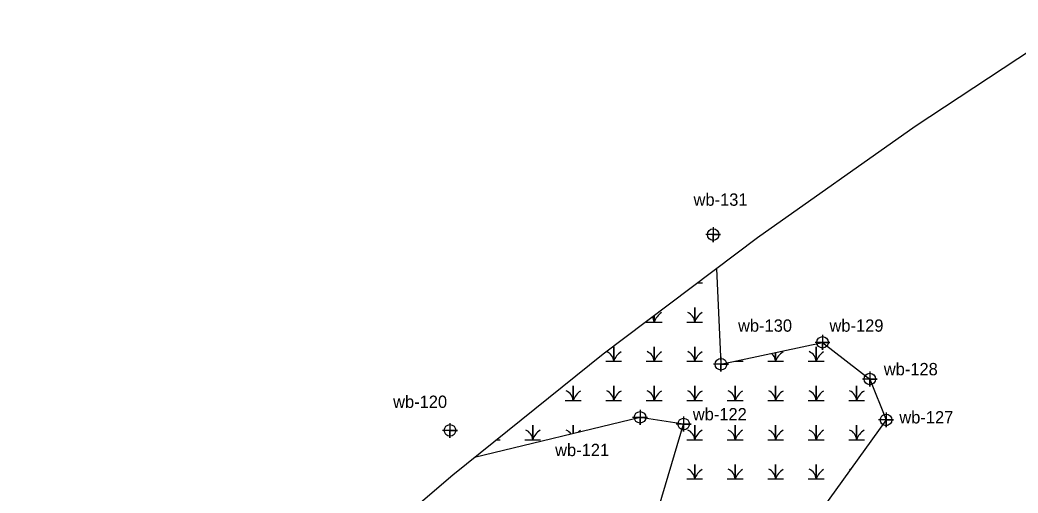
# Model space of a CAD drawing. Extents: x 2379288 to 2381905, y 330670 to 333511.
# Drawn here: x 2380487.2 to 2380892.7, y 332911.6 to 333103.7 of the extents above; entities that cross this region are included whole.
import ezdxf

# ---------------------------------------------------------------- set-up
doc = ezdxf.new("R2010")
doc.units = 0
for name, color, linetype in [('Default', 7, 'Continuous'), ('Exist Environmental Wetland Boundary', 7, 'Continuous'), ('Exist Environmental Wetland Boundary Cogo Number', 7, 'Continuous'), ('Exist Environmental Wetland Boundary Cogo Point CELL', 7, 'Continuous'), ('Exist Hydro Swamp or Marsh', 7, 'Continuous')]:
    doc.layers.add(name, color=color, linetype=linetype)

msp = doc.modelspace()

# ---------------------------------------------------------------- linework, layer by layer
at = {"layer": 'Default'}
msp.add_lwpolyline([(2379288.07, 330873.37), (2380109.3, 332268.58), (2380147.86, 332331.82), (2380190.73, 332397.51), (2380235.65, 332461.81), (2380282.57, 332524.66), (2380331.46, 332586), (2380382.25, 332645.77), (2380434.91, 332703.9), (2380489.37, 332760.35), (2380545.59, 332815.05), (2380603.5, 332867.95), (2380663.06, 332918.99), (2380724.19, 332968.13), (2380786.85, 333015.32), (2380850.96, 333060.51), (2380916.47, 333103.65)], dxfattribs=at)
at = {"layer": 'Exist Environmental Wetland Boundary'}
msp.add_lwpolyline([(2380770.18, 333002.77), (2380771.99, 332963.9), (2380813.28, 332972.8), (2380832.48, 332957.91), (2380839.06, 332941.31), (2380810.01, 332900.93), (2380770.09, 332869.86), (2380731.49, 332867.02), (2380743.29, 332893.96), (2380756.83, 332939.63), (2380739.11, 332942.35), (2380671.81, 332926.03)], dxfattribs=at)
at = {"layer": 'Exist Environmental Wetland Boundary Cogo Point CELL'}
for points in [[(2380768.82, 333019.52), (2380768.82, 333013.52), (2380768.82, 333016.52), (2380771.82, 333016.52), (2380765.82, 333016.52)], [(2380813.28, 332975.8), (2380813.28, 332969.8), (2380813.28, 332972.8), (2380816.28, 332972.8), (2380810.28, 332972.8)], [(2380771.99, 332966.9), (2380771.99, 332960.9), (2380771.99, 332963.9), (2380774.99, 332963.9), (2380768.99, 332963.9)], [(2380832.48, 332960.91), (2380832.48, 332954.91), (2380832.48, 332957.91), (2380835.48, 332957.91), (2380829.48, 332957.91)], [(2380739.11, 332945.35), (2380739.11, 332939.35), (2380739.11, 332942.35), (2380742.11, 332942.35), (2380736.11, 332942.35)], [(2380756.83, 332942.63), (2380756.83, 332936.63), (2380756.83, 332939.63), (2380759.83, 332939.63), (2380753.83, 332939.63)], [(2380839.06, 332944.31), (2380839.06, 332938.31), (2380839.06, 332941.31), (2380842.06, 332941.31), (2380836.06, 332941.31)], [(2380661.89, 332940.05), (2380661.89, 332934.05), (2380661.89, 332937.05), (2380664.89, 332937.05), (2380658.89, 332937.05)]]:
    msp.add_lwpolyline(points, dxfattribs=at)
for centre in [(2380768.82, 333016.52), (2380813.28, 332972.8), (2380771.99, 332963.9), (2380832.48, 332957.91), (2380739.11, 332942.35), (2380756.83, 332939.63), (2380839.06, 332941.31), (2380661.89, 332937.05)]:
    msp.add_circle(centre, 2.34, dxfattribs=at)
at = {"layer": 'Exist Hydro Swamp or Marsh'}
for p, q in [((2380762.44, 332996.94), (2380764.53, 332996.94)), ((2380680.82, 332933.27), (2380682.27, 332933.27))]:
    msp.add_line(p, q, dxfattribs=at)
for points in [[(2380758.08, 332981.02), (2380761.31, 332981.02), (2380761.31, 332986.94), (2380761.31, 332981.02), (2380764.53, 332981.02)], [(2380741.63, 332981.02), (2380744.85, 332981.02), (2380744.85, 332983.69)], [(2380744.85, 332983.69), (2380744.85, 332981.02), (2380748.08, 332981.02)], [(2380725.18, 332965.1), (2380728.4, 332965.1), (2380728.4, 332971.02), (2380728.4, 332965.1), (2380731.63, 332965.1)], [(2380741.63, 332965.1), (2380744.85, 332965.1), (2380744.85, 332971.02), (2380744.85, 332965.1), (2380748.08, 332965.1)], [(2380758.08, 332965.1), (2380761.31, 332965.1), (2380761.31, 332971.02), (2380761.31, 332965.1), (2380764.53, 332965.1)], [(2380807.43, 332965.1), (2380810.66, 332965.1), (2380810.66, 332971.02), (2380810.66, 332965.1), (2380813.88, 332965.1)], [(2380790.98, 332965.1), (2380794.21, 332965.1), (2380794.21, 332968.68)], [(2380794.21, 332968.68), (2380794.21, 332965.1), (2380797.43, 332965.1)], [(2380777.61, 332965.1), (2380777.76, 332965.1), (2380777.76, 332965.14)], [(2380777.76, 332965.14), (2380777.76, 332965.1), (2380780.98, 332965.1)], [(2380708.73, 332949.19), (2380711.95, 332949.19), (2380711.95, 332955.1), (2380711.95, 332949.19), (2380715.18, 332949.19)], [(2380725.18, 332949.19), (2380728.4, 332949.19), (2380728.4, 332955.1), (2380728.4, 332949.19), (2380731.63, 332949.19)], [(2380741.63, 332949.19), (2380744.85, 332949.19), (2380744.85, 332955.1), (2380744.85, 332949.19), (2380748.08, 332949.19)], [(2380758.08, 332949.19), (2380761.31, 332949.19), (2380761.31, 332955.1), (2380761.31, 332949.19), (2380764.53, 332949.19)], [(2380774.53, 332949.19), (2380777.76, 332949.19), (2380777.76, 332955.1), (2380777.76, 332949.19), (2380780.98, 332949.19)], [(2380790.98, 332949.19), (2380794.21, 332949.19), (2380794.21, 332955.1), (2380794.21, 332949.19), (2380797.43, 332949.19)], [(2380807.43, 332949.19), (2380810.66, 332949.19), (2380810.66, 332955.1), (2380810.66, 332949.19), (2380813.88, 332949.19)], [(2380823.88, 332949.19), (2380827.11, 332949.19), (2380827.11, 332955.1), (2380827.11, 332949.19), (2380830.34, 332949.19)], [(2380692.27, 332933.27), (2380695.5, 332933.27), (2380695.5, 332939.19), (2380695.5, 332933.27), (2380698.73, 332933.27)], [(2380711.95, 332935.76), (2380711.95, 332939.19), (2380711.95, 332935.76)], [(2380758.08, 332933.27), (2380761.31, 332933.27), (2380761.31, 332939.19), (2380761.31, 332933.27), (2380764.53, 332933.27)], [(2380774.53, 332933.27), (2380777.76, 332933.27), (2380777.76, 332939.19), (2380777.76, 332933.27), (2380780.98, 332933.27)], [(2380790.98, 332933.27), (2380794.21, 332933.27), (2380794.21, 332939.19), (2380794.21, 332933.27), (2380797.43, 332933.27)], [(2380807.43, 332933.27), (2380810.66, 332933.27), (2380810.66, 332939.19), (2380810.66, 332933.27), (2380813.88, 332933.27)], [(2380823.88, 332933.27), (2380827.11, 332933.27), (2380827.11, 332939.19), (2380827.11, 332933.27), (2380830.34, 332933.27)], [(2380758.08, 332917.35), (2380761.31, 332917.35), (2380761.31, 332923.27), (2380761.31, 332917.35), (2380764.53, 332917.35)], [(2380774.53, 332917.35), (2380777.76, 332917.35), (2380777.76, 332923.27), (2380777.76, 332917.35), (2380780.98, 332917.35)], [(2380790.98, 332917.35), (2380794.21, 332917.35), (2380794.21, 332923.27), (2380794.21, 332917.35), (2380797.43, 332917.35)], [(2380807.43, 332917.35), (2380810.66, 332917.35), (2380810.66, 332923.27), (2380810.66, 332917.35), (2380813.88, 332917.35)]]:
    msp.add_lwpolyline(points, dxfattribs=at)
for centre, radius, start, end in [((2380740.25, 332980.69), 4.61, 4.1403, 32.4261), ((2380751.69, 332978.75), 7.21, 122.1274, 161.6222), ((2380756.71, 332980.69), 4.61, 4.1403, 67.535), ((2380768.15, 332978.75), 7.21, 122.1274, 161.6222), ((2380723.8, 332964.77), 4.61, 4.1403, 67.535), ((2380735.24, 332962.83), 7.21, 122.1274, 161.6222), ((2380740.25, 332964.77), 4.61, 4.1403, 67.535), ((2380751.69, 332962.83), 7.21, 122.1274, 161.6222), ((2380756.71, 332964.77), 4.61, 4.1403, 67.535), ((2380768.15, 332962.83), 7.21, 122.1274, 161.6222), ((2380789.61, 332964.77), 4.61, 4.1403, 50.4107), ((2380801.05, 332962.83), 7.21, 122.1274, 161.6222), ((2380806.06, 332964.77), 4.61, 4.1403, 67.535), ((2380817.5, 332962.83), 7.21, 122.1274, 161.6222), ((2380773.16, 332964.77), 4.61, 4.1403, 4.5399), ((2380784.6, 332962.83), 7.21, 161.3277, 161.6222), ((2380707.35, 332948.85), 4.61, 4.1403, 67.535), ((2380718.79, 332946.91), 7.21, 122.1274, 161.6222), ((2380723.8, 332948.85), 4.61, 4.1403, 67.535), ((2380735.24, 332946.91), 7.21, 122.1274, 161.6222), ((2380740.25, 332948.85), 4.61, 4.1403, 67.535), ((2380751.69, 332946.91), 7.21, 122.1274, 161.6222), ((2380756.71, 332948.85), 4.61, 4.1403, 67.535), ((2380768.15, 332946.91), 7.21, 122.1274, 161.6222), ((2380773.16, 332948.85), 4.61, 4.1403, 67.535), ((2380784.6, 332946.91), 7.21, 122.1274, 161.6222), ((2380789.61, 332948.85), 4.61, 4.1403, 67.535), ((2380801.05, 332946.91), 7.21, 122.1274, 161.6222), ((2380806.06, 332948.85), 4.61, 4.1403, 67.535), ((2380817.5, 332946.91), 7.21, 122.1274, 161.6222), ((2380822.51, 332948.85), 4.61, 4.1403, 67.535), ((2380833.95, 332946.91), 7.21, 122.1274, 161.6222), ((2380690.9, 332932.94), 4.61, 4.1403, 67.535), ((2380702.34, 332931), 7.21, 122.1274, 161.6222), ((2380707.35, 332932.94), 4.61, 34.7435, 67.535), ((2380718.79, 332931), 7.21, 122.1274, 133.6377), ((2380756.71, 332932.94), 4.61, 4.1403, 67.535), ((2380768.15, 332931), 7.21, 122.1274, 161.6222), ((2380773.16, 332932.94), 4.61, 4.1403, 67.535), ((2380784.6, 332931), 7.21, 122.1274, 161.6222), ((2380789.61, 332932.94), 4.61, 4.1403, 67.535), ((2380801.05, 332931), 7.21, 122.1274, 161.6222), ((2380806.06, 332932.94), 4.61, 4.1403, 67.535), ((2380817.5, 332931), 7.21, 122.1274, 161.6222), ((2380822.51, 332932.94), 4.61, 4.1403, 67.535), ((2380833.95, 332931), 7.21, 122.1274, 161.6222), ((2380756.71, 332917.02), 4.61, 4.1403, 67.535), ((2380768.15, 332915.08), 7.21, 122.1274, 161.6222), ((2380773.16, 332917.02), 4.61, 4.1403, 67.535), ((2380784.6, 332915.08), 7.21, 122.1274, 161.6222), ((2380789.61, 332917.02), 4.61, 4.1403, 67.535), ((2380801.05, 332915.08), 7.21, 122.1274, 161.6222), ((2380806.06, 332917.02), 4.61, 4.1403, 67.535), ((2380817.5, 332915.08), 7.21, 122.1274, 161.6222), ((2380822.51, 332917.02), 4.61, 63.6802, 67.535)]:
    msp.add_arc(centre, radius, start, end, dxfattribs=at)

# ---------------------------------------------------------------- texts
at = {"layer": 'Exist Environmental Wetland Boundary Cogo Number'}
for s, p in [('wb-131', (2380760.85, 333028.23)), ('wb-130', (2380778.93, 332977.11)), ('wb-129', (2380816.08, 332977.11)), ('wb-128', (2380838.16, 332959.43)), ('wb-120', (2380638.78, 332946.18)), ('wb-122', (2380760.55, 332941.13)), ('wb-127', (2380844.47, 332939.87)), ('wb-121', (2380704.61, 332926.61))]:
    msp.add_text(s, height=5, dxfattribs=at).set_placement(p)

doc.saveas('drawing.dxf')
